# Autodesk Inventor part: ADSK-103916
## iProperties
Shininess: 0.0
Created: 2001-01
Part Number: ADSK-103916
Document SubType Name: Modeling
Stock Number: ADSK-103916
Density: 1 g/cm^3
Density: 0.0
Volumn: 0.0
Area: 0.0
PropertySet Name: Model Information
Control State: 0
Master: False
Checked Out: False
Author: gao
